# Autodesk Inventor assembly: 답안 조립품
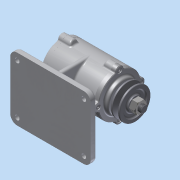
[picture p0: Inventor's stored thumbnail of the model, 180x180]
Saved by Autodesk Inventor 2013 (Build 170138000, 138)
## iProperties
Created: 2015-12
Part Number: 답안 조립품
Document SubType Name: Assembly
Designer: Administrator
Author: Administrator
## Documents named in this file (11)
- C:\Users\Administrator\Desktop\451208V1031\답안 조립품.iam
- C:\Users\Administrator\Desktop\451208V1031\1 본체.ipt
- C:\Users\Administrator\Desktop\451208V1031\451208V1031\커버.ipt
- C:\Users\Administrator\Desktop\451208V1031\451208V1031\베어링 6204.ipt
- C:\Users\Administrator\Desktop\451208V1031\451208V1031\V-벨트풀리.ipt
- C:\Users\Administrator\Desktop\451208V1031\451208V1031\축.ipt
- C:\Users\Administrator\Desktop\451208V1031\451208V1031\커버2.ipt
- C:\Users\Administrator\Desktop\451208V1031\451208V1031\키(4 x 4 x 12).ipt
- C:\Users\Administrator\Desktop\451208V1031\451208V1031\너트 M12x1.25.ipt
- C:\Users\Administrator\Desktop\451208V1031\451208V1031\볼트 M4 x 12.ipt
- C:\Users\Administrator\Desktop\451208V1031\451208V1031\오일실.ipt
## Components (7 placed, 6 different names)
1. 1 본체:1
2. KS B 2023 6204 - 20 x 47 x 14:1
3. KS B 2023 6204 - 20 x 47 x 14:2
4. V-벨트풀리:1 — 각도:2
5. KS B 1311 (I) 4 x 4 x 12:1 — 각도:1, 각도:2
6. KS B 1012 클래스 1 일반 - 미터 M12x1.25:1
7. KS B 2804 D D - 20 32 8:1
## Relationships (2: Angle 2)
- 각도:1 [Angle]: KS B 1311 (I) 4 x 4 x 12:1
- 각도:2 [Angle]: V-벨트풀리:1 ↔ KS B 1311 (I) 4 x 4 x 12:1
